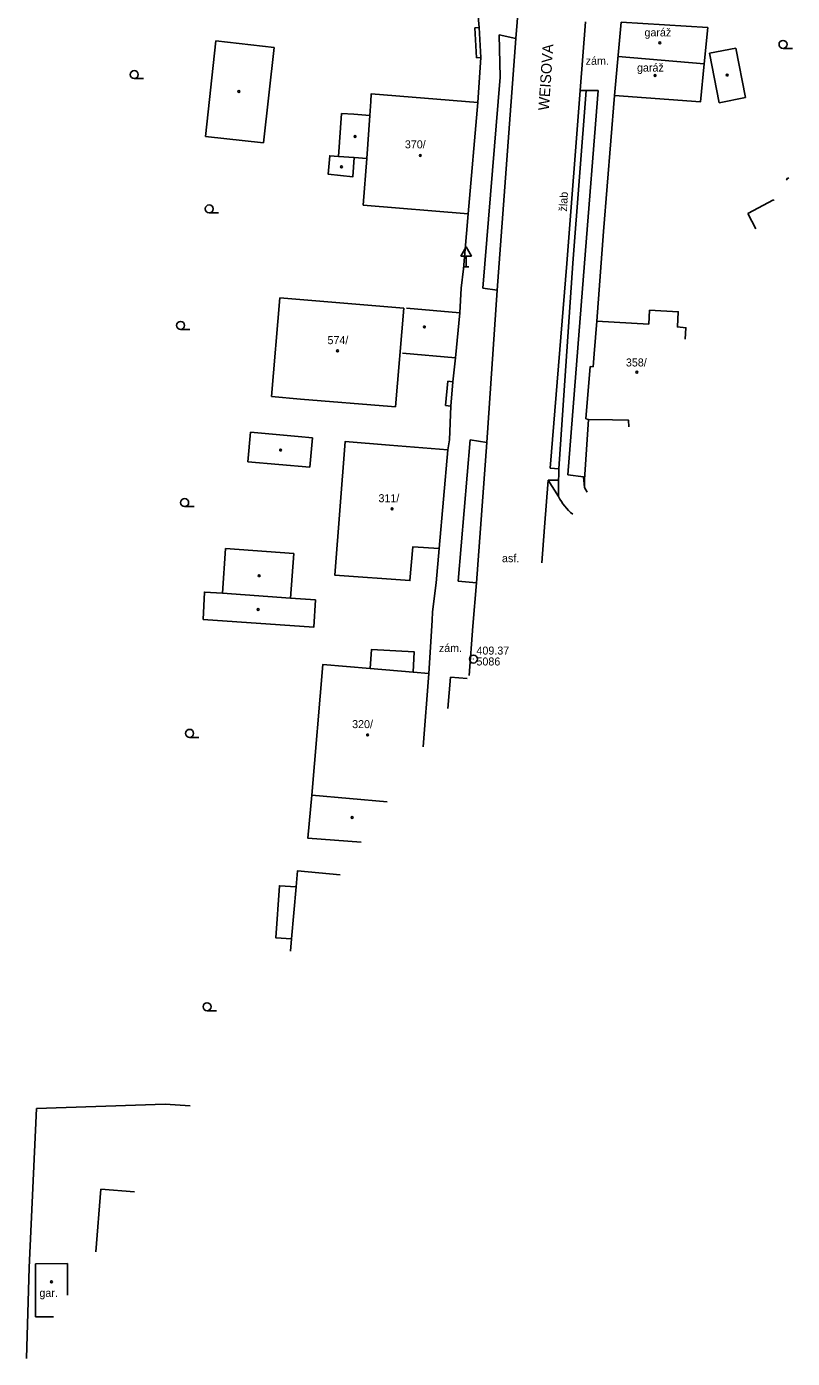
# Model space of a CAD drawing. Extents: x -737488 to -734267, y -1145775 to -1142573.
# Drawn here: x -736723.3 to -736651.6, y -1144689.1 to -1144564.3 of the extents above; entities that cross this region are included whole.
import ezdxf

# ---------------------------------------------------------------- set-up
doc = ezdxf.new("R2010")
doc.units = 0
for name, color, linetype in [('Vrstva 1', 7, 'Continuous'), ('Vrstva 10', 7, 'Continuous'), ('Vrstva 13', 7, 'Continuous'), ('Vrstva 14', 7, 'Continuous'), ('Vrstva 19', 7, 'Continuous'), ('Vrstva 3', 7, 'Continuous'), ('Vrstva 4', 7, 'Continuous'), ('Vrstva 5', 7, 'Continuous'), ('Vrstva 6', 7, 'Continuous'), ('Vrstva 8', 7, 'Continuous'), ('Vrstva 9', 7, 'Continuous')]:
    doc.layers.add(name, color=color, linetype=linetype)

# ---------------------------------------------------------------- blocks, each defined once
blk = doc.blocks.new('1.079')
at = {"layer": 'Vrstva 1'}
for radius in [0.75, 0.001]:
    blk.add_circle((0, -0.001), radius, dxfattribs=at)
blk = doc.blocks.new('3.040')
at = {"layer": 'Vrstva 1'}
blk.add_line((0, -0.75), (1.75, -0.75), dxfattribs=at)
blk.add_circle((0, 0), 0.75, dxfattribs=at)
blk = doc.blocks.new('4.020')
at = {"layer": 'Vrstva 1'}
blk.add_circle((0, 0), 0.175, dxfattribs=at)
blk = doc.blocks.new('5.270')
at = {"layer": 'Vrstva 1'}
for p, q in [((0, 3.732), (-1, 2)), ((0, 3.732), (1, 2)), ((-1, 2), (1, 2)), ((-0.5, 0), (0.5, 0)), ((0, 0), (0, 2))]:
    blk.add_line(p, q, dxfattribs=at)

msp = doc.modelspace()

# ---------------------------------------------------------------- linework, layer by layer
at = {"layer": 'Vrstva 10'}
for points in [[(-736677.46, -1144565.47), (-736676.86, -1144557.77)], [(-736671.46, -1144570.33), (-736670.96, -1144563.91)], [(-736679.21, -1144589.03), (-736677.46, -1144565.47)], [(-736679.02, -1144565.11), (-736677.46, -1144565.47)], [(-736678.94, -1144569.09), (-736679.02, -1144565.11)], [(-736680.55, -1144588.84), (-736678.94, -1144569.09)], [(-736672.71, -1144586.54), (-736671.46, -1144570.33)], [(-736672.14, -1144586.5), (-736670.87, -1144570.33)], [(-736670.87, -1144570.33), (-736671.46, -1144570.33)], [(-736671.05, -1144586.5), (-736669.77, -1144570.33)], [(-736669.77, -1144570.33), (-736670.87, -1144570.33)], [(-736674.26, -1144605.71), (-736672.71, -1144586.54)], [(-736673.43, -1144605.79), (-736672.14, -1144586.5)], [(-736672.59, -1144606.36), (-736671.05, -1144586.5)], [(-736679.21, -1144589.03), (-736680.55, -1144588.84)], [(-736680.2, -1144603.31), (-736679.21, -1144589.03)], [(-736682.88, -1144616.31), (-736681.74, -1144603.07)], [(-736681.74, -1144603.07), (-736680.2, -1144603.31)], [(-736681.17, -1144616.47), (-736680.2, -1144603.31)], [(-736675.05, -1144614.58), (-736674.8, -1144611.25), (-736674.45, -1144606.83)], [(-736674.45, -1144606.83), (-736673.49, -1144608.38)], [(-736673.46, -1144606.84), (-736674.45, -1144606.83)], [(-736673.43, -1144605.79), (-736674.26, -1144605.71)], [(-736673.46, -1144606.84), (-736673.49, -1144608.38)], [(-736673.43, -1144605.79), (-736673.45, -1144606.34), (-736673.46, -1144606.84)], [(-736671.04, -1144607.52), (-736671.13, -1144606.54), (-736672.59, -1144606.36)], [(-736681.17, -1144616.47), (-736682.88, -1144616.31)], [(-736681.49, -1144620.52), (-736681.17, -1144616.47)], [(-736681.49, -1144620.52), (-736681.84, -1144625.14)], [(-736683.6, -1144625.3), (-736683.84, -1144628.23)], [(-736682.02, -1144625.42), (-736683.6, -1144625.3)]]:
    msp.add_lwpolyline(points, dxfattribs=at)
msp.add_arc((-736668.46, -1144605.69), 5.7, 208.1637, 229.8127, dxfattribs=at)
at = {"layer": 'Vrstva 4'}
for points in [[(-736681.3, -1144564.45), (-736680.9, -1144564.43)], [(-736680.75, -1144567.24), (-736680.9, -1144564.43)], [(-736668.23, -1144570.81), (-736667.6, -1144563.94)], [(-736681.15, -1144567.26), (-736681.3, -1144564.45)], [(-736681.15, -1144567.26), (-736680.75, -1144567.24)], [(-736681.95, -1144581.89), (-736681.03, -1144571.44)], [(-736683.12, -1144595.38), (-736682.73, -1144591.16)], [(-736670.22, -1144596.22), (-736670.13, -1144595.02), (-736669.89, -1144591.93)], [(-736670.93, -1144601.1), (-736670.52, -1144596.19)], [(-736670.22, -1144596.22), (-736670.52, -1144596.19)], [(-736683.85, -1144597.56), (-736684.05, -1144599.85)], [(-736683.37, -1144597.62), (-736683.85, -1144597.56)], [(-736683.57, -1144599.91), (-736683.37, -1144597.62)], [(-736683.57, -1144599.91), (-736684.05, -1144599.85)], [(-736670.66, -1144601.15), (-736670.93, -1144601.1)], [(-736684.65, -1144613.26), (-736683.84, -1144604.01)], [(-736685.62, -1144624.96), (-736686.17, -1144631.83)], [(-736716.35, -1144673.29), (-736716.83, -1144679.15)], [(-736713.19, -1144673.53), (-736716.35, -1144673.29)], [(-736722.48, -1144680.27), (-736719.48, -1144680.25)], [(-736722.47, -1144685.25), (-736722.48, -1144680.27)], [(-736719.47, -1144683.23), (-736719.48, -1144680.25)], [(-736720.78, -1144685.24), (-736722.47, -1144685.25)]]:
    msp.add_lwpolyline(points, dxfattribs=at)
at = {"layer": 'Vrstva 5'}
for points in [[(-736668.23, -1144570.81), (-736660.17, -1144571.39), (-736659.82, -1144567.83), (-736659.49, -1144564.43), (-736667.6, -1144563.94)], [(-736705.58, -1144565.69), (-736706.56, -1144574.63)], [(-736700.12, -1144566.29), (-736705.58, -1144565.69)], [(-736701.1, -1144575.23), (-736700.12, -1144566.29)], [(-736656.85, -1144566.36), (-736659.33, -1144566.84)], [(-736659.33, -1144566.84), (-736658.43, -1144571.47)], [(-736655.95, -1144570.99), (-736656.85, -1144566.36)], [(-736667.89, -1144567.14), (-736659.82, -1144567.83)], [(-736681.03, -1144571.44), (-736691.02, -1144570.63), (-736691.06, -1144571.37), (-736691.14, -1144572.66)], [(-736658.43, -1144571.47), (-736655.95, -1144570.99)], [(-736694.1, -1144576.5), (-736693.81, -1144572.47)], [(-736693.81, -1144572.47), (-736692.66, -1144572.55)], [(-736692.66, -1144572.55), (-736691.14, -1144572.66)], [(-736691.14, -1144572.66), (-736691.44, -1144576.7)], [(-736706.56, -1144574.63), (-736701.1, -1144575.23)], [(-736694.1, -1144576.5), (-736694.9, -1144576.45), (-736695.06, -1144578.16), (-736692.75, -1144578.42), (-736692.61, -1144576.61)], [(-736692.61, -1144576.61), (-736694.1, -1144576.5)], [(-736691.44, -1144576.7), (-736692.61, -1144576.61)], [(-736691.44, -1144576.7), (-736691.77, -1144581.07), (-736681.95, -1144581.89)], [(-736652.11, -1144578.61), (-736651.91, -1144578.51)], [(-736652.05, -1144578.72), (-736652.11, -1144578.61)], [(-736653.32, -1144580.56), (-736655.75, -1144581.85)], [(-736653.28, -1144580.64), (-736653.32, -1144580.56)], [(-736655.75, -1144581.85), (-736654.98, -1144583.3)], [(-736699.59, -1144589.77), (-736700.36, -1144599.01)], [(-736687.98, -1144590.73), (-736699.59, -1144589.77)], [(-736688.75, -1144599.97), (-736687.98, -1144590.73)], [(-736682.73, -1144591.16), (-736687.71, -1144590.72)], [(-736661.61, -1144593.62), (-736661.53, -1144592.56), (-736662.34, -1144592.49), (-736662.26, -1144591.07), (-736664.94, -1144590.92), (-736665.02, -1144592.22), (-736669.89, -1144591.93)], [(-736683.12, -1144595.38), (-736688.1, -1144594.94)], [(-736700.36, -1144599.01), (-736697.65, -1144599.24)], [(-736697.65, -1144599.24), (-736689.12, -1144599.94)], [(-736689.12, -1144599.94), (-736688.75, -1144599.97)], [(-736670.66, -1144601.15), (-736668.43, -1144601.18), (-736666.93, -1144601.21), (-736666.89, -1144601.86)], [(-736702.58, -1144605.13), (-736702.34, -1144602.36)], [(-736702.34, -1144602.36), (-736697.88, -1144602.75)], [(-736697.88, -1144602.75), (-736696.53, -1144602.87)], [(-736696.53, -1144602.87), (-736696.77, -1144605.64)], [(-736683.84, -1144604.01), (-736689.3, -1144603.56), (-736693.45, -1144603.22), (-736694.42, -1144615.76), (-736687.4, -1144616.26), (-736687.12, -1144613.08), (-736684.65, -1144613.26)], [(-736696.77, -1144605.64), (-736702.58, -1144605.13)], [(-736704.66, -1144613.24), (-736704.97, -1144617.42)], [(-736698.26, -1144613.72), (-736704.66, -1144613.24)], [(-736698.58, -1144617.9), (-736698.26, -1144613.72)], [(-736698.58, -1144617.9), (-736696.25, -1144618.07), (-736696.41, -1144620.62), (-736706.76, -1144619.9), (-736706.65, -1144617.33), (-736704.97, -1144617.42)], [(-736704.97, -1144617.42), (-736698.58, -1144617.9)], [(-736687.09, -1144624.83), (-736686.99, -1144622.94), (-736690.98, -1144622.7), (-736691.11, -1144624.49)], [(-736685.62, -1144624.96), (-736687.09, -1144624.83), (-736691.11, -1144624.49), (-736695.54, -1144624.11), (-736696.6, -1144636.35), (-736696.95, -1144640.4), (-736691.97, -1144640.78)], [(-736689.53, -1144637), (-736696.6, -1144636.35)], [(-736693.94, -1144643.82), (-736697.93, -1144643.46), (-736698.06, -1144644.96), (-736698.49, -1144649.84), (-736698.59, -1144650.99)], [(-736698.06, -1144644.96), (-736699.62, -1144644.85), (-736699.95, -1144649.74), (-736698.49, -1144649.84)]]:
    msp.add_lwpolyline(points, dxfattribs=at)
at = {"layer": 'Vrstva 9'}
for points in [[(-736680.9, -1144564.43), (-736681.27, -1144560.18)], [(-736681.03, -1144571.44), (-736680.75, -1144567.24)], [(-736669.25, -1144583.55), (-736668.23, -1144570.81)], [(-736682.38, -1144587.03), (-736681.95, -1144581.89)], [(-736669.89, -1144591.93), (-736669.25, -1144583.55)], [(-736682.58, -1144588.86), (-736682.38, -1144587.03)], [(-736682.73, -1144591.16), (-736682.58, -1144588.86)], [(-736683.37, -1144597.62), (-736683.12, -1144595.38)], [(-736683.68, -1144603.07), (-736683.57, -1144599.91)], [(-736671.03, -1144606.78), (-736670.66, -1144601.15)], [(-736683.84, -1144604.01), (-736683.68, -1144603.07)], [(-736671.04, -1144607.52), (-736671.03, -1144606.78)], [(-736670.8, -1144607.96), (-736671.04, -1144607.52)], [(-736684.93, -1144616.47), (-736684.65, -1144613.26)], [(-736685.29, -1144619.18), (-736684.93, -1144616.47)], [(-736685.29, -1144619.18), (-736685.3, -1144620)], [(-736685.3, -1144620), (-736685.62, -1144624.96)], [(-736710.32, -1144665.32), (-736722.38, -1144665.74)], [(-736707.98, -1144665.48), (-736710.32, -1144665.32)], [(-736722.38, -1144665.74), (-736723.07, -1144680.63)], [(-736723.31, -1144689.14), (-736723.07, -1144680.63)]]:
    msp.add_lwpolyline(points, dxfattribs=at)

# ---------------------------------------------------------------- block references
at = {"layer": 'Vrstva 1', "xscale": 0.5, "yscale": 0.5}
msp.add_blockref('1.079', (-736681.44, -1144623.61), dxfattribs=at)
at = {"layer": 'Vrstva 3', "xscale": 0.5, "yscale": 0.5}
for p in [(-736652.44, -1144566.01), (-736713.22, -1144568.84), (-736706.2, -1144581.42), (-736708.88, -1144592.34), (-736708.5, -1144608.95), (-736708.04, -1144630.57), (-736706.4, -1144656.19)]:
    msp.add_blockref('3.040', p, dxfattribs=at)
at = {"layer": 'Vrstva 8', "xscale": 0.5, "yscale": 0.5}
for p in [(-736663.99, -1144565.87), (-736664.43, -1144568.93), (-736657.67, -1144568.88), (-736703.42, -1144570.42), (-736692.54, -1144574.64), (-736686.42, -1144576.42), (-736693.81, -1144577.49), (-736686.04, -1144592.49), (-736694.18, -1144594.73), (-736666.13, -1144596.73), (-736699.51, -1144604.02), (-736689.07, -1144609.53), (-736701.52, -1144615.8), (-736701.62, -1144618.97), (-736691.36, -1144630.72), (-736692.81, -1144638.46), (-736720.98, -1144681.97)]:
    msp.add_blockref('4.020', p, dxfattribs=at)
at = {"layer": 'Vrstva 9', "xscale": 0.5, "yscale": 0.5}
msp.add_blockref('5.270', (-736682.12, -1144586.85), dxfattribs=at)

# ---------------------------------------------------------------- texts
at = {"layer": 'Vrstva 13'}
msp.add_text('WEISOVA', height=1, rotation=86.034, dxfattribs=at).set_placement((-736674.38, -1144572.23))
at = {"layer": 'Vrstva 14'}
for s, p in [('garáž', (-736665.42, -1144565.26)), ('zám.', (-736670.93, -1144567.92)), ('garáž', (-736666.12, -1144568.56)), ('asf.', (-736678.77, -1144614.53)), ('zám.', (-736684.68, -1144622.95)), ('gar.', (-736722.11, -1144683.38))]:
    msp.add_text(s, height=0.75, dxfattribs=at).set_placement(p)
msp.add_text('žlab', height=0.75, rotation=86.864, dxfattribs=at).set_placement((-736672.69, -1144581.68))
at = {"layer": 'Vrstva 19'}
for s, p in [(' 409.37', (-736681.44, -1144623.19)), (' 5086', (-736681.44, -1144624.21))]:
    msp.add_text(s, height=0.75, dxfattribs=at).set_placement(p)
at = {"layer": 'Vrstva 6'}
for s, p in [('370/', (-736687.87, -1144575.75)), ('574/', (-736695.12, -1144594.1)), ('358/', (-736667.16, -1144596.19)), ('311/', (-736690.34, -1144608.91)), ('320/', (-736692.81, -1144630.08))]:
    msp.add_text(s, height=0.75, dxfattribs=at).set_placement(p)

doc.saveas('drawing.dxf')
